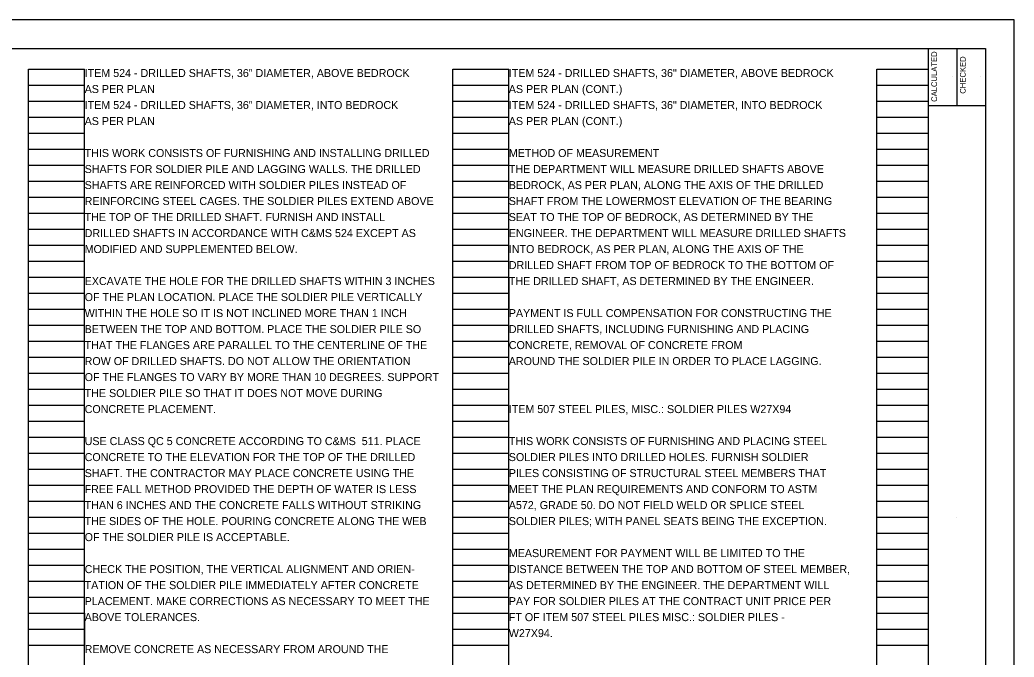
# Model space of a CAD drawing. Extents: x 0 to 34, y 0 to 22.
# Drawn here: x 16.61 to 34, y 10.85 to 22 of the extents above; entities that cross this region are included whole.
import ezdxf

# ---------------------------------------------------------------- set-up
doc = ezdxf.new("R2010")
doc.units = 0
for name, color, linetype in [('SC_Scratch1', 7, 'Continuous'), ('SH_Border', 7, 'Continuous'), ('SH_Cut_Line', 7, 'Continuous'), ('SH_Data', 7, 'Continuous'), ('SH_Text', 7, 'Continuous'), ('TX_P_Misc', 7, 'Continuous')]:
    doc.layers.add(name, color=color, linetype=linetype)

msp = doc.modelspace()

# ---------------------------------------------------------------- linework, layer by layer
at = {"layer": 'SC_Scratch1'}
for p, q in [((25.16, 17.5), (25.16, 16.94)), ((17.74, 11.62), (17.74, 11.06))]:
    msp.add_line(p, q, dxfattribs=at)
at = {"layer": 'SH_Border'}
for p, q in [((32.5, 0.5), (32.5, 21.5)), ((33, 21.5), (33, 20.5)), ((32.5, 20.5), (33.5, 20.5))]:
    msp.add_line(p, q, dxfattribs=at)
msp.add_lwpolyline([(2, 21.5), (33.5, 21.5), (33.5, 0.5), (2, 0.5)], close=True, dxfattribs=at)
at = {"layer": 'SH_Cut_Line'}
msp.add_lwpolyline([(0, 0), (34, 0), (34, 22), (0, 22)], close=True, dxfattribs=at)
at = {"layer": 'SH_Data'}
for p, q in [((16.76, 0.98), (16.76, 21.14)), ((16.76, 21.14), (17.74, 21.14)), ((17.74, 0.98), (17.74, 21.14)), ((24.18, 0.98), (24.18, 21.14)), ((24.18, 21.14), (25.16, 21.14)), ((25.16, 0.98), (25.16, 21.14)), ((31.6, 0.98), (31.6, 21.14)), ((31.6, 21.14), (32.5, 21.14)), ((32.5, 0.98), (32.5, 21.14)), ((32.92, 21.004), (32.92, 21.004)), ((33.42, 21.004), (33.42, 21.004)), ((16.76, 20.86), (17.74, 20.86)), ((24.18, 20.86), (25.16, 20.86)), ((31.6, 20.86), (32.5, 20.86)), ((16.76, 20.58), (17.74, 20.58)), ((24.18, 20.58), (25.16, 20.58)), ((31.6, 20.58), (32.5, 20.58)), ((16.76, 20.3), (17.74, 20.3)), ((24.18, 20.3), (25.16, 20.3)), ((31.6, 20.3), (32.5, 20.3)), ((16.76, 20.02), (17.74, 20.02)), ((24.18, 20.02), (25.16, 20.02)), ((31.6, 20.02), (32.5, 20.02)), ((16.76, 19.74), (17.74, 19.74)), ((24.18, 19.74), (25.16, 19.74)), ((31.6, 19.74), (32.5, 19.74)), ((16.76, 19.46), (17.74, 19.46)), ((24.18, 19.46), (25.16, 19.46)), ((31.6, 19.46), (32.5, 19.46)), ((16.76, 19.18), (17.74, 19.18)), ((24.18, 19.18), (25.16, 19.18)), ((31.6, 19.18), (32.5, 19.18)), ((16.76, 18.9), (17.74, 18.9)), ((24.18, 18.9), (25.16, 18.9)), ((31.6, 18.9), (32.5, 18.9)), ((16.76, 18.62), (17.74, 18.62)), ((24.18, 18.62), (25.16, 18.62)), ((31.6, 18.62), (32.5, 18.62)), ((16.76, 18.34), (17.74, 18.34)), ((24.18, 18.34), (25.16, 18.34)), ((31.6, 18.34), (32.5, 18.34)), ((16.76, 18.06), (17.74, 18.06)), ((24.18, 18.06), (25.16, 18.06)), ((31.6, 18.06), (32.5, 18.06)), ((16.76, 17.78), (17.74, 17.78)), ((24.18, 17.78), (25.16, 17.78)), ((31.6, 17.78), (32.5, 17.78)), ((16.76, 17.5), (17.74, 17.5)), ((24.18, 17.5), (25.16, 17.5)), ((31.6, 17.5), (32.5, 17.5)), ((16.76, 17.22), (17.74, 17.22)), ((24.18, 17.22), (25.16, 17.22)), ((31.6, 17.22), (32.5, 17.22)), ((16.76, 16.94), (17.74, 16.94)), ((24.18, 16.94), (25.16, 16.94)), ((31.6, 16.94), (32.5, 16.94)), ((16.76, 16.66), (17.74, 16.66)), ((24.18, 16.66), (25.16, 16.66)), ((31.6, 16.66), (32.5, 16.66)), ((16.76, 16.38), (17.74, 16.38)), ((24.18, 16.38), (25.16, 16.38)), ((31.6, 16.38), (32.5, 16.38)), ((16.76, 16.1), (17.74, 16.1)), ((24.18, 16.1), (25.16, 16.1)), ((31.6, 16.1), (32.5, 16.1)), ((16.76, 15.82), (17.74, 15.82)), ((24.18, 15.82), (25.16, 15.82)), ((31.6, 15.82), (32.5, 15.82)), ((16.76, 15.54), (17.74, 15.54)), ((24.18, 15.54), (25.16, 15.54)), ((31.6, 15.54), (32.5, 15.54)), ((16.76, 15.26), (17.74, 15.26)), ((24.18, 15.26), (25.16, 15.26)), ((31.6, 15.26), (32.5, 15.26)), ((16.76, 14.98), (17.74, 14.98)), ((24.18, 14.98), (25.16, 14.98)), ((31.6, 14.98), (32.5, 14.98)), ((16.76, 14.7), (17.74, 14.7)), ((24.18, 14.7), (25.16, 14.7)), ((31.6, 14.7), (32.5, 14.7)), ((16.76, 14.42), (17.74, 14.42)), ((24.18, 14.42), (25.16, 14.42)), ((31.6, 14.42), (32.5, 14.42)), ((16.76, 14.14), (17.74, 14.14)), ((24.18, 14.14), (25.16, 14.14)), ((31.6, 14.14), (32.5, 14.14)), ((16.76, 13.86), (17.74, 13.86)), ((24.18, 13.86), (25.16, 13.86)), ((31.6, 13.86), (32.5, 13.86)), ((16.76, 13.58), (17.74, 13.58)), ((24.18, 13.58), (25.16, 13.58)), ((31.6, 13.58), (32.5, 13.58)), ((16.76, 13.3), (17.74, 13.3)), ((24.18, 13.3), (25.16, 13.3)), ((31.6, 13.3), (32.5, 13.3)), ((33, 13.292), (33, 13.292)), ((16.76, 13.02), (17.74, 13.02)), ((24.18, 13.02), (25.16, 13.02)), ((31.6, 13.02), (32.5, 13.02)), ((16.76, 12.74), (17.74, 12.74)), ((24.18, 12.74), (25.16, 12.74)), ((31.6, 12.74), (32.5, 12.74)), ((16.76, 12.46), (17.74, 12.46)), ((24.18, 12.46), (25.16, 12.46)), ((31.6, 12.46), (32.5, 12.46)), ((16.76, 12.18), (17.74, 12.18)), ((24.18, 12.18), (25.16, 12.18)), ((31.6, 12.18), (32.5, 12.18)), ((16.76, 11.9), (17.74, 11.9)), ((24.18, 11.9), (25.16, 11.9)), ((31.6, 11.9), (32.5, 11.9)), ((16.76, 11.62), (17.74, 11.62)), ((24.18, 11.62), (25.16, 11.62)), ((31.6, 11.62), (32.5, 11.62)), ((16.76, 11.34), (17.74, 11.34)), ((24.18, 11.34), (25.16, 11.34)), ((31.6, 11.34), (32.5, 11.34)), ((16.76, 11.06), (17.74, 11.06)), ((24.18, 11.06), (25.16, 11.06)), ((31.6, 11.06), (32.5, 11.06))]:
    msp.add_line(p, q, dxfattribs=at)

# ---------------------------------------------------------------- texts
for s, p in [('CALCULATED', (32.652, 20.565)), ('CHECKED', (33.152, 20.708))]:
    msp.add_text(s, height=0.1, rotation=90, dxfattribs=at).set_placement(p)
at = {"layer": 'SH_Text'}
for s, p in [('ITEM 524 - DRILLED SHAFTS, 36" DIAMETER, ABOVE BEDROCK', (17.74, 21)), ('ITEM 524 - DRILLED SHAFTS, 36" DIAMETER, ABOVE BEDROCK', (25.16, 21)), ('AS PER PLAN', (17.74, 20.72)), ('AS PER PLAN (CONT.)', (25.16, 20.72)), ('ITEM 524 - DRILLED SHAFTS, 36" DIAMETER, INTO BEDROCK', (17.74, 20.44)), ('ITEM 524 - DRILLED SHAFTS, 36" DIAMETER, INTO BEDROCK', (25.16, 20.44)), ('AS PER PLAN', (17.74, 20.16)), ('AS PER PLAN (CONT.)', (25.16, 20.16)), ('THIS WORK CONSISTS OF FURNISHING AND INSTALLING DRILLED', (17.74, 19.6)), ('SHAFTS FOR SOLDIER PILE AND LAGGING WALLS. THE DRILLED', (17.74, 19.32)), ('SHAFTS ARE REINFORCED WITH SOLDIER PILES INSTEAD OF', (17.74, 19.04)), ('REINFORCING STEEL CAGES. THE SOLDIER PILES EXTEND ABOVE', (17.74, 18.76)), ('THE TOP OF THE DRILLED SHAFT. FURNISH AND INSTALL', (17.74, 18.48)), ('DRILLED SHAFTS IN ACCORDANCE WITH C&MS 524 EXCEPT AS', (17.74, 18.2)), ('MODIFIED AND SUPPLEMENTED BELOW.', (17.74, 17.92)), ('EXCAVATE THE HOLE FOR THE DRILLED SHAFTS WITHIN 3 INCHES', (17.74, 17.36)), ('OF THE PLAN LOCATION. PLACE THE SOLDIER PILE VERTICALLY', (17.74, 17.08)), ('WITHIN THE HOLE SO IT IS NOT INCLINED MORE THAN 1 INCH', (17.74, 16.8)), ('BETWEEN THE TOP AND BOTTOM. PLACE THE SOLDIER PILE SO', (17.74, 16.52)), ('THAT THE FLANGES ARE PARALLEL TO THE CENTERLINE OF THE', (17.74, 16.24)), ('ROW OF DRILLED SHAFTS. DO NOT ALLOW THE ORIENTATION', (17.74, 15.96)), ('OF THE FLANGES TO VARY BY MORE THAN 10 DEGREES. SUPPORT', (17.74, 15.68)), ('THE SOLDIER PILE SO THAT IT DOES NOT MOVE DURING', (17.74, 15.4)), ('CONCRETE PLACEMENT.', (17.74, 15.12)), ('ITEM 507 STEEL PILES, MISC.: SOLDIER PILES W27X94', (25.16, 15.12)), ('USE CLASS QC 5 CONCRETE ACCORDING TO C&MS  511. PLACE', (17.74, 14.56)), ('THIS WORK CONSISTS OF FURNISHING AND PLACING STEEL', (25.16, 14.56)), ('CONCRETE TO THE ELEVATION FOR THE TOP OF THE DRILLED', (17.74, 14.28)), ('SOLDIER PILES INTO DRILLED HOLES. FURNISH SOLDIER', (25.16, 14.28)), ('SHAFT. THE CONTRACTOR MAY PLACE CONCRETE USING THE', (17.74, 14)), ('PILES CONSISTING OF STRUCTURAL STEEL MEMBERS THAT', (25.16, 14)), ('FREE FALL METHOD PROVIDED THE DEPTH OF WATER IS LESS', (17.74, 13.72)), ('MEET THE PLAN REQUIREMENTS AND CONFORM TO ASTM', (25.16, 13.72)), ('THAN 6 INCHES AND THE CONCRETE FALLS WITHOUT STRIKING', (17.74, 13.44)), ('A572, GRADE 50. DO NOT FIELD WELD OR SPLICE STEEL', (25.16, 13.44)), ('THE SIDES OF THE HOLE. POURING CONCRETE ALONG THE WEB', (17.74, 13.16)), ('SOLDIER PILES; WITH PANEL SEATS BEING THE EXCEPTION.', (25.16, 13.16)), ('OF THE SOLDIER PILE IS ACCEPTABLE.', (17.74, 12.88)), ('MEASUREMENT FOR PAYMENT WILL BE LIMITED TO THE ', (25.16, 12.6)), ('CHECK THE POSITION, THE VERTICAL ALIGNMENT AND ORIEN-', (17.74, 12.32)), ('DISTANCE BETWEEN THE TOP AND BOTTOM OF STEEL MEMBER, ', (25.16, 12.32)), ('TATION OF THE SOLDIER PILE IMMEDIATELY AFTER CONCRETE', (17.74, 12.04)), ('AS DETERMINED BY THE ENGINEER. THE DEPARTMENT WILL', (25.16, 12.04)), ('PLACEMENT. MAKE CORRECTIONS AS NECESSARY TO MEET THE', (17.74, 11.76)), ('PAY FOR SOLDIER PILES AT THE CONTRACT UNIT PRICE PER', (25.16, 11.76)), ('ABOVE TOLERANCES.', (17.74, 11.48)), ('FT OF ITEM 507 STEEL PILES MISC.: SOLDIER PILES - ', (25.16, 11.48)), ('W27X94.', (25.16, 11.2)), ('REMOVE CONCRETE AS NECESSARY FROM AROUND THE', (17.74, 10.92))]:
    msp.add_text(s, height=0.14, dxfattribs=at).set_placement(p)
at = {"layer": 'TX_P_Misc'}
for s, p in [('METHOD OF MEASUREMENT', (25.16, 19.6)), ('THE DEPARTMENT WILL MEASURE DRILLED SHAFTS ABOVE', (25.16, 19.32)), ('BEDROCK, AS PER PLAN, ALONG THE AXIS OF THE DRILLED', (25.16, 19.04)), ('SHAFT FROM THE LOWERMOST ELEVATION OF THE BEARING', (25.16, 18.76)), ('SEAT TO THE TOP OF BEDROCK, AS DETERMINED BY THE', (25.16, 18.48)), ('ENGINEER. THE DEPARTMENT WILL MEASURE DRILLED SHAFTS', (25.16, 18.2)), ('INTO BEDROCK, AS PER PLAN, ALONG THE AXIS OF THE', (25.16, 17.92)), ('DRILLED SHAFT FROM TOP OF BEDROCK TO THE BOTTOM OF', (25.16, 17.64)), ('THE DRILLED SHAFT, AS DETERMINED BY THE ENGINEER.', (25.16, 17.36)), ('PAYMENT IS FULL COMPENSATION FOR CONSTRUCTING THE', (25.16, 16.8)), ('DRILLED SHAFTS, INCLUDING FURNISHING AND PLACING', (25.16, 16.52)), ('CONCRETE, REMOVAL OF CONCRETE FROM', (25.16, 16.24)), ('AROUND THE SOLDIER PILE IN ORDER TO PLACE LAGGING.', (25.16, 15.96))]:
    msp.add_text(s, height=0.14, dxfattribs=at).set_placement(p)

doc.saveas('drawing.dxf')
